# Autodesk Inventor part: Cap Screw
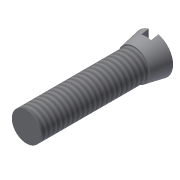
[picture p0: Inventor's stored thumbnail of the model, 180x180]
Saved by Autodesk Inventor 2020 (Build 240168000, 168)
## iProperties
Created: 2002-02
Part Number: Cap Screw
Document SubType Name: Modeling
Designer: ***
Density: 1 g/cm^3
Material: Generic
Mass: 0.736586 g
Surface Area: 5.87035 cm^2
Volume: 0.736586 cm^3
Appearance: Default
Control State: 0
Master: False
Checked Out: False
Shininess: 77.0
Length Units: 11269
Angle Units: 11279
Time Units: 11290
Mass Units: 11283
Length Display Precision: 3
Angle Display Precision: 2
Density: 0.0
Volumn: 0.0
Area: 0.0
PropertySet Name: Model Information
Author: ***
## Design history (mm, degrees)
sketch "Sketch1"
  geometry: L1 (0, 27.83)-(4, 27.83); L2 (4, 27.83)-(3.25, 23.83); L3 (3.25, 23.83)-(0, 23.83); L4 (0, 23.83)-(0, 27.83)
  constraints: 8 end point, 1 horizontal, 1 parallel, 1 perpendicular, 1 point on line
  dimensions: "d2" = 4 distance from line of L1 L2.end; "d5" = 8 diameter of L1.end L4; "d6" = 6.5 diameter of L3.start L4; "d14" = 4 distance of L3.end L1.start
revolve "Revolution1" sketch "Sketch1" stored, may be unused: angle "d7" = 90 deg
sketch "Sketch2"
  geometry: C1 r 3 at (0, 0)
  constraints: 1 centre point
  dimensions: "d8" = 6 diameter of C1
extrude "Extrusion1" join sketch "Sketch2" distance "d9" = 22; taper "d10" = 0 deg
sketch "Sketch3"
  geometry: L1 (-1, 28.967)-(1, 28.967); L2 (1, 28.967)-(1, 26.33); L3 (1, 26.33)-(-1, 26.33); L4 (-1, 26.33)-(-1, 28.967); L5 (-4, 27.83)-(4, 27.83) reference
  constraints: 8 end point, 2 parallel, 1 horizontal, 1 perpendicular
  dimensions: "d11" = 2 distance of L1.start L1.end; "d15" = 1.5 distance between parallel lines of L5 L3
extrude "Extrusion2" cut sketch "Sketch3" extent not by distance; stored distance "d12" = 24; taper "d13" = 0 deg
thread "Thread1" dims "d16" = 22, "d17" = 0
body "Solid1"
